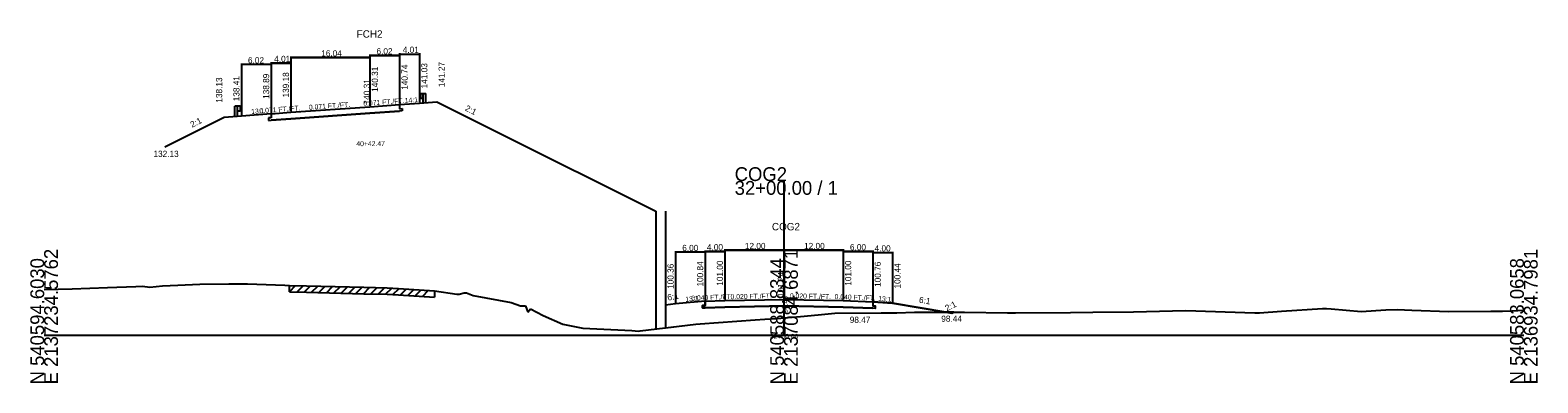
# Model space of a CAD drawing. Extents: x -13397 to 2303, y -10 to 39059.
# Drawn here: x 997.2 to 1302.8, y 3990.3 to 4061.8 of the extents above; entities that cross this region are included whole.
import ezdxf

# ---------------------------------------------------------------- set-up
doc = ezdxf.new("R2010")
doc.units = 0
for name, color, linetype in [('Level 20', 7, 'Continuous'), ('Level 5', 7, 'Continuous'), ('Level 53', 7, 'Continuous'), ('Level 54', 7, 'Continuous'), ('Level 55', 7, 'Continuous'), ('Level 7', 7, 'Continuous'), ('RD_GPK_XS_Cell', 7, 'Continuous'), ('RD_XS_EwShp', 7, 'Continuous'), ('RD_XS_ExGround', 7, 'Continuous'), ('RD_XS_ExPaveRet', 7, 'Continuous'), ('RD_XS_MedBWall', 7, 'Continuous'), ('RD_XS_Pave', 7, 'Continuous'), ('RD_XS_TX_Baseline', 7, 'Continuous'), ('RD_XS_TX_Elev_EX', 7, 'Continuous'), ('RD_XS_TX_Elev_PR', 7, 'Continuous'), ('RD_XS_TX_Station', 7, 'Continuous')]:
    doc.layers.add(name, color=color, linetype=linetype)

msp = doc.modelspace()

# ---------------------------------------------------------------- linework, layer by layer
at = {"layer": 'Level 20'}
for p, q in [((1050, 4056.46), (1050, 4045.38)), ((1050, 4056.46), (1050, 4045.38)), ((1050, 4056.46), (1050, 4045.38)), ((1050, 4056.46), (1050, 4045.38)), ((1066.04, 4056.89), (1066.04, 4046.51)), ((1066.04, 4056.89), (1066.04, 4046.51)), ((1066.04, 4056.89), (1066.04, 4046.51)), ((1066.04, 4056.69), (1072.06, 4056.69)), ((1072.06, 4056.69), (1066.04, 4056.69)), ((1072.06, 4056.69), (1066.04, 4056.69)), ((1066.04, 4056.46), (1066.04, 4046.51)), ((1066.04, 4056.46), (1066.04, 4046.51)), ((1066.04, 4056.46), (1066.04, 4046.51)), ((1066.04, 4056.46), (1066.04, 4046.51)), ((1072.06, 4057.18), (1072.06, 4046.94)), ((1072.06, 4056.98), (1076.07, 4056.98)), ((1072.06, 4056.89), (1072.06, 4046.94)), ((1072.06, 4056.89), (1072.06, 4046.94)), ((1072.06, 4056.89), (1072.06, 4046.94)), ((1076.07, 4057.18), (1076.07, 4047.23)), ((1039.98, 4055.04), (1039.98, 4044.61)), ((1045.99, 4054.84), (1039.98, 4054.84)), ((1045.99, 4055.33), (1045.99, 4045.09)), ((1045.99, 4055.33), (1045.99, 4045.09)), ((1045.99, 4055.33), (1045.99, 4045.09)), ((1045.99, 4055.13), (1050, 4055.13)), ((1045.99, 4055.13), (1050, 4055.13)), ((1050, 4055.13), (1045.99, 4055.13)), ((1045.99, 4055.04), (1045.99, 4045.09)), ((1050, 4056.26), (1066.04, 4056.26)), ((1050, 4056.26), (1066.04, 4056.26)), ((1066.04, 4056.26), (1050, 4056.26)), ((1066.04, 4056.26), (1050, 4056.26)), ((1050, 4055.33), (1050, 4045.38)), ((1050, 4055.33), (1050, 4045.38)), ((1050, 4055.33), (1050, 4045.38)), ((1076.07, 4047.03), (1079.58, 4047.27)), ((1076.09, 4048.84), (1076.21, 4048.93)), ((1076.09, 4048.74), (1076.21, 4048.65)), ((1076.09, 4048.31), (1076.21, 4048.4)), ((1076.09, 4048.21), (1076.21, 4048.12)), ((1076.22, 4048.94), (1076.3, 4048.95)), ((1076.22, 4048.11), (1076.3, 4048.1)), ((1076.23, 4048.6), (1076.23, 4048.45)), ((1076.3, 4049.01), (1076.3, 4048.04)), ((1076.3, 4049.01), (1076.85, 4049.01)), ((1076.3, 4048.04), (1076.85, 4048.04)), ((1076.85, 4047.03), (1076.85, 4049.01)), ((1076.85, 4049.01), (1077.41, 4049.01)), ((1077.41, 4047.03), (1077.41, 4049.01)), ((1079.58, 4047.27), (1091.61, 4041.27)), ((1039.98, 4044.41), (1036.47, 4044.13)), ((1038.64, 4044.41), (1038.64, 4046.4)), ((1039.2, 4046.4), (1038.64, 4046.4)), ((1039.2, 4044.41), (1039.2, 4046.4)), ((1039.75, 4046.4), (1039.2, 4046.4)), ((1039.75, 4045.43), (1039.2, 4045.43)), ((1039.75, 4046.4), (1039.75, 4045.43)), ((1039.82, 4046.32), (1039.75, 4046.34)), ((1039.82, 4045.5), (1039.75, 4045.49)), ((1039.82, 4045.99), (1039.82, 4045.83)), ((1039.95, 4046.23), (1039.84, 4046.32)), ((1039.95, 4046.13), (1039.84, 4046.03)), ((1039.95, 4045.7), (1039.84, 4045.79)), ((1039.95, 4045.6), (1039.84, 4045.5)), ((1045.99, 4044.89), (1039.98, 4044.41)), ((1045.99, 4044.89), (1050, 4045.18)), ((1045.99, 4044.89), (1045.99, 4044.06)), ((1050, 4045.18), (1066.04, 4046.31)), ((1066.04, 4044.98), (1050, 4043.84)), ((1066.04, 4044.98), (1050, 4043.84)), ((1050, 4043.84), (1066.04, 4044.98)), ((1050, 4043.84), (1066.04, 4044.98)), ((1066.04, 4046.31), (1072.06, 4046.74)), ((1072.06, 4045.41), (1066.04, 4044.98)), ((1066.04, 4044.98), (1072.06, 4045.41)), ((1066.04, 4044.98), (1072.06, 4045.41)), ((1072.06, 4046.74), (1076.07, 4047.03)), ((1072.06, 4046.74), (1072.06, 4045.91)), ((1072.06, 4045.91), (1072.56, 4045.94)), ((1072.56, 4045.44), (1072.06, 4045.41)), ((1072.56, 4045.94), (1072.56, 4045.44)), ((1036.47, 4044.13), (1024.44, 4038.13)), ((1045.99, 4044.06), (1045.49, 4044.02)), ((1045.49, 4044.02), (1045.49, 4043.52)), ((1045.49, 4043.52), (1045.99, 4043.56)), ((1050, 4043.84), (1045.99, 4043.56)), ((1050, 4043.84), (1045.99, 4043.56)), ((1045.99, 4043.56), (1050, 4043.84)), ((1091.61, 4041.27), (1124, 4025.12))]:
    msp.add_line(p, q, dxfattribs=at)
for centre, radius, start, end in [((1076.13, 4048.79), 0.0651, 129.0336, 230.9663), ((1076.13, 4048.26), 0.0651, 129.0336, 230.9663), ((1076.16, 4048.45), 0.0651, 302.9895, 0), ((1076.22, 4048.91), 0.026, 90, 129.0505), ((1076.16, 4048.6), 0.0651, 0, 45), ((1076.22, 4048.14), 0.026, 230.9496, 270), ((1039.82, 4046.3), 0.026, 50.9495, 90), ((1039.89, 4045.99), 0.0651, 135, 180), ((1039.89, 4045.83), 0.0651, 180, 237.0105), ((1039.82, 4045.53), 0.026, 270, 309.0504), ((1039.91, 4046.18), 0.0651, 309.0337, 50.9664), ((1039.91, 4045.65), 0.0651, 309.0337, 50.9664)]:
    msp.add_arc(centre, radius, start, end, dxfattribs=at)
at = {"layer": 'Level 5'}
for p, q in [((1134, 4006.01), (1133.5, 4005.99)), ((1133.5, 4005.99), (1133.5, 4005.49)), ((1133.5, 4005.49), (1134, 4005.51)), ((1134, 4006.84), (1134, 4006.01)), ((1138, 4005.67), (1134, 4005.51)), ((1138, 4005.67), (1134, 4005.51)), ((1138, 4005.67), (1134, 4005.51)), ((1134, 4005.51), (1138, 4005.67)), ((1150, 4005.91), (1138, 4005.67)), ((1150, 4005.91), (1138, 4005.67)), ((1150, 4005.91), (1138, 4005.67)), ((1138, 4005.67), (1150, 4005.91)), ((1138, 4005.67), (1150, 4005.91)), ((1162, 4005.67), (1150, 4005.91)), ((1162, 4005.67), (1150, 4005.91)), ((1150, 4005.91), (1162, 4005.67)), ((1150, 4005.91), (1162, 4005.67)), ((1150, 4005.91), (1162, 4005.67)), ((1168, 4005.43), (1162, 4005.67)), ((1162, 4005.67), (1168, 4005.43)), ((1162, 4005.67), (1168, 4005.43)), ((1162, 4005.67), (1168, 4005.43)), ((1168, 4006.76), (1168, 4005.93)), ((1168, 4005.93), (1168.5, 4005.91)), ((1168.5, 4005.41), (1168, 4005.43)), ((1168.5, 4005.91), (1168.5, 4005.41))]:
    msp.add_line(p, q, dxfattribs=at)
at = {"layer": 'Level 54'}
for p, q in [((1128, 4016.99), (1128, 4006.56)), ((1134, 4016.79), (1128, 4016.79)), ((1134, 4017.15), (1134, 4007.04)), ((1134, 4017.15), (1134, 4007.04)), ((1134, 4017.15), (1134, 4007.04)), ((1134, 4017.15), (1134, 4007.04)), ((1134, 4016.99), (1134, 4007.04)), ((1134, 4016.95), (1138, 4016.95)), ((1134, 4016.95), (1138, 4016.95)), ((1134, 4016.95), (1138, 4016.95)), ((1138, 4016.95), (1134, 4016.95)), ((1138, 4017.39), (1138, 4007.2)), ((1138, 4017.39), (1138, 4007.2)), ((1138, 4017.39), (1138, 4007.2)), ((1138, 4017.39), (1138, 4007.2)), ((1138, 4017.39), (1138, 4007.2)), ((1138, 4017.19), (1150, 4017.19)), ((1138, 4017.19), (1150, 4017.19)), ((1138, 4017.19), (1150, 4017.19)), ((1150, 4017.19), (1138, 4017.19)), ((1150, 4017.19), (1138, 4017.19)), ((1138, 4017.15), (1138, 4007.2)), ((1138, 4017.15), (1138, 4007.2)), ((1138, 4017.15), (1138, 4007.2)), ((1138, 4017.15), (1138, 4007.2)), ((1150, 4017.39), (1150, 4007.44)), ((1150, 4017.39), (1150, 4007.44)), ((1150, 4017.39), (1150, 4007.44)), ((1150, 4017.39), (1150, 4007.44)), ((1150, 4017.39), (1150, 4007.44)), ((1150, 4017.39), (1150, 4007.44)), ((1150, 4017.39), (1150, 4007.44)), ((1150, 4017.39), (1150, 4007.44)), ((1150, 4017.39), (1150, 4007.44)), ((1150, 4017.39), (1150, 4007.44)), ((1150, 4017.19), (1162, 4017.19)), ((1150, 4017.19), (1162, 4017.19)), ((1162, 4017.19), (1150, 4017.19)), ((1162, 4017.19), (1150, 4017.19)), ((1162, 4017.19), (1150, 4017.19)), ((1162, 4017.39), (1162, 4007.2)), ((1162, 4017.39), (1162, 4007.2)), ((1162, 4017.39), (1162, 4007.2)), ((1162, 4017.39), (1162, 4007.2)), ((1162, 4017.39), (1162, 4007.2)), ((1162, 4017.15), (1162, 4007.2)), ((1162, 4017.15), (1162, 4007.2)), ((1162, 4017.15), (1162, 4007.2)), ((1162, 4017.15), (1162, 4007.2)), ((1162, 4016.95), (1168, 4016.95)), ((1168, 4016.95), (1162, 4016.95)), ((1168, 4016.95), (1162, 4016.95)), ((1168, 4016.95), (1162, 4016.95)), ((1168, 4017.15), (1168, 4006.96)), ((1168, 4017.15), (1168, 4006.96)), ((1168, 4017.15), (1168, 4006.96)), ((1168, 4017.15), (1168, 4006.96)), ((1168, 4016.91), (1168, 4006.96)), ((1168, 4016.71), (1172, 4016.71)), ((1172, 4016.91), (1172, 4006.64))]:
    msp.add_line(p, q, dxfattribs=at)
at = {"layer": 'Level 7'}
for p, q in [((1128, 4006.36), (1126, 4006.03)), ((1126, 4006.03), (1126, 4001.45)), ((1134, 4006.84), (1128, 4006.36)), ((1168, 4006.76), (1172, 4006.44)), ((1172, 4006.44), (1184, 4004.44)), ((1184, 4004.44), (1184.41, 4004.64))]:
    msp.add_line(p, q, dxfattribs=at)
at = {"layer": 'RD_GPK_XS_Cell'}
for p, q in [((1150, 4000), (1150, 4031.24)), ((1000, 4000), (1150, 4000)), ((1150, 4000), (1300, 4000))]:
    msp.add_line(p, q, dxfattribs=at)
at = {"layer": 'RD_XS_EwShp'}
for points in [[(1128, 4006.36), (1126, 4006.03), (1126, 4001.45), (1132.12, 4002.18), (1132.97, 4002.28), (1144.16, 4003.11), (1146.1, 4003.21), (1148.69, 4003.38), (1150, 4003.49), (1153.34, 4003.76), (1156.94, 4004.12), (1160.29, 4004.44), (1169.73, 4004.49), (1172.85, 4004.51), (1176.43, 4004.61), (1182.82, 4004.64), (1172, 4006.44), (1168, 4006.76), (1168, 4005.93), (1168.5, 4005.91), (1168.5, 4005.41), (1168, 4005.43), (1162, 4005.67), (1150, 4005.91), (1138, 4005.67), (1134, 4005.51), (1133.5, 4005.49), (1133.5, 4005.99), (1134, 4006.01), (1134, 4006.84)], [(1182.82, 4004.64), (1184, 4004.44), (1184.41, 4004.64)]]:
    msp.add_lwpolyline(points, close=True, dxfattribs=at)
at = {"layer": 'RD_XS_ExGround'}
for p, q in [((1000, 4009.21), (1005.66, 4009.36)), ((1005.66, 4009.36), (1012.85, 4009.66)), ((1012.85, 4009.66), (1018.61, 4009.87)), ((1018.61, 4009.87), (1019.92, 4009.89)), ((1019.92, 4009.89), (1021.4, 4009.73)), ((1021.4, 4009.73), (1023.99, 4009.95)), ((1023.99, 4009.95), (1027.11, 4010.15)), ((1027.11, 4010.15), (1031.55, 4010.33)), ((1031.55, 4010.33), (1037.46, 4010.41)), ((1037.46, 4010.41), (1041.23, 4010.39)), ((1041.23, 4010.39), (1048.82, 4010.1)), ((1048.82, 4010.1), (1049.71, 4010.06)), ((1049.71, 4010.06), (1053.16, 4010)), ((1053.16, 4010), (1064.83, 4009.68)), ((1064.83, 4009.68), (1069.55, 4009.56)), ((1069.55, 4009.56), (1071.85, 4009.45)), ((1071.85, 4009.45), (1079.15, 4009)), ((1079.15, 4009), (1083.69, 4008.27)), ((1083.69, 4008.27), (1084.15, 4008.29)), ((1084.15, 4008.29), (1085.12, 4008.53)), ((1085.12, 4008.53), (1085.64, 4008.54)), ((1085.64, 4008.54), (1086.96, 4008.02)), ((1086.96, 4008.02), (1094.66, 4006.57)), ((1094.66, 4006.57), (1096.6, 4005.93)), ((1096.6, 4005.93), (1097.56, 4005.9)), ((1097.56, 4005.9), (1098.04, 4004.62)), ((1098.04, 4004.62), (1098.63, 4005.31)), ((1098.63, 4005.31), (1101.2, 4003.97)), ((1156.94, 4004.12), (1160.29, 4004.44)), ((1160.29, 4004.44), (1169.73, 4004.49)), ((1169.73, 4004.49), (1172.85, 4004.51)), ((1172.85, 4004.51), (1176.43, 4004.61)), ((1176.43, 4004.61), (1186.58, 4004.65)), ((1186.58, 4004.65), (1195.29, 4004.53)), ((1195.29, 4004.53), (1196.03, 4004.51)), ((1196.03, 4004.51), (1196.92, 4004.53)), ((1196.92, 4004.53), (1208.08, 4004.59)), ((1208.08, 4004.59), (1212.63, 4004.62)), ((1212.63, 4004.62), (1220.86, 4004.69)), ((1220.86, 4004.69), (1228.75, 4004.88)), ((1228.75, 4004.88), (1231.47, 4005)), ((1231.47, 4005), (1245.45, 4004.53)), ((1245.45, 4004.53), (1246.01, 4004.53)), ((1246.01, 4004.53), (1246.43, 4004.51)), ((1246.43, 4004.51), (1250.87, 4004.83)), ((1250.87, 4004.83), (1259.21, 4005.36)), ((1259.21, 4005.36), (1259.99, 4005.41)), ((1259.99, 4005.41), (1260.96, 4005.29)), ((1260.96, 4005.29), (1267.05, 4004.78)), ((1267.05, 4004.78), (1271.99, 4005.09)), ((1271.99, 4005.09), (1274.29, 4005.2)), ((1274.29, 4005.2), (1277.27, 4005.07)), ((1277.27, 4005.07), (1284.78, 4004.79)), ((1284.78, 4004.79), (1293.34, 4004.86)), ((1293.34, 4004.86), (1295.65, 4004.86)), ((1295.65, 4004.86), (1297.56, 4004.94)), ((1297.56, 4004.94), (1300, 4005.03)), ((1101.2, 4003.97), (1105.17, 4002.24)), ((1105.17, 4002.24), (1109.21, 4001.39)), ((1109.21, 4001.39), (1119.14, 4000.91)), ((1120.87, 4000.84), (1132.12, 4002.18)), ((1132.12, 4002.18), (1132.97, 4002.28)), ((1132.97, 4002.28), (1144.16, 4003.11)), ((1144.16, 4003.11), (1146.1, 4003.21)), ((1146.1, 4003.21), (1148.69, 4003.38)), ((1148.69, 4003.38), (1150, 4003.49)), ((1150, 4003.49), (1153.34, 4003.76)), ((1153.34, 4003.76), (1156.94, 4004.12)), ((1119.14, 4000.91), (1120.47, 4000.8)), ((1120.47, 4000.8), (1120.87, 4000.84))]:
    msp.add_line(p, q, dxfattribs=at)
at = {"layer": 'RD_XS_ExPaveRet'}
for p, q in [((1049.71, 4008.76), (1049.71, 4010.06)), ((1049.71, 4008.76), (1050.99, 4010.04)), ((1049.71, 4008.76), (1053.16, 4008.7)), ((1051.21, 4008.73), (1052.49, 4010.01)), ((1052.72, 4008.71), (1053.98, 4009.98)), ((1053.16, 4008.7), (1064.83, 4008.38)), ((1054.22, 4008.67), (1055.48, 4009.93)), ((1055.72, 4008.63), (1056.98, 4009.89)), ((1057.22, 4008.59), (1058.48, 4009.85)), ((1058.72, 4008.55), (1059.98, 4009.81)), ((1060.22, 4008.5), (1061.48, 4009.77)), ((1061.72, 4008.46), (1062.98, 4009.73)), ((1063.22, 4008.42), (1064.48, 4009.69)), ((1064.72, 4008.38), (1065.98, 4009.65)), ((1064.83, 4008.38), (1069.55, 4008.26)), ((1066.22, 4008.34), (1067.48, 4009.61)), ((1067.72, 4008.3), (1068.98, 4009.57)), ((1069.22, 4008.27), (1070.46, 4009.51)), ((1069.55, 4008.26), (1071.85, 4008.15)), ((1070.72, 4008.2), (1071.96, 4009.44)), ((1071.85, 4008.15), (1079.15, 4007.7)), ((1072.22, 4008.13), (1073.44, 4009.35)), ((1073.72, 4008.03), (1074.94, 4009.26)), ((1075.22, 4007.94), (1076.44, 4009.17)), ((1076.72, 4007.85), (1077.94, 4009.08)), ((1079.15, 4009), (1079.15, 4007.7))]:
    msp.add_line(p, q, dxfattribs=at)
at = {"layer": 'RD_XS_MedBWall'}
for p, q in [((1124, 4025.12), (1124, 4001.21)), ((1126, 4025.12), (1126, 4006.03))]:
    msp.add_line(p, q, dxfattribs=at)
at = {"layer": 'RD_XS_Pave'}
for p, q in [((1134, 4006.84), (1138, 4007)), ((1138, 4007), (1150, 4007.24)), ((1150, 4007.24), (1162, 4007)), ((1162, 4007), (1168, 4006.76))]:
    msp.add_line(p, q, dxfattribs=at)

# ---------------------------------------------------------------- texts
at = {"layer": 'Level 20'}
for s, height, p in [('FCH2', 1.5, (1063.36, 4060.31)), ('4.01', 1.25, (1046.64, 4055.38)), ('4.01', 1.25, (1046.64, 4055.38)), ('4.01', 1.25, (1046.64, 4055.38)), ('16.04', 1.25, (1056.17, 4056.51)), ('16.04', 1.25, (1056.17, 4056.51)), ('16.04', 1.25, (1056.17, 4056.51)), ('16.04', 1.25, (1056.17, 4056.51)), ('6.02', 1.25, (1067.38, 4056.94)), ('6.02', 1.25, (1067.38, 4056.94)), ('6.02', 1.25, (1067.38, 4056.94)), ('4.01', 1.25, (1072.71, 4057.23)), ('6.02', 1.25, (1041.32, 4055.09)), ('40+42.47', 1, (1063.29, 4038.31)), ('132.13', 1.25, (1022.16, 4036.13))]:
    msp.add_text(s, height=height, dxfattribs=at).set_placement(p)
for s, height, rotation, p in [('140.31', 1.25, 90, (1067.67, 4049.31)), ('140.31', 1.25, 90, (1067.67, 4049.31)), ('140.74', 1.25, 90, (1073.69, 4049.74)), ('141.03', 1.25, 90, (1077.7, 4050.03)), ('141.27', 1.25, 90, (1081.21, 4050.27)), ('138.13', 1.25, 90, (1036.09, 4047.13)), ('138.41', 1.25, 90, (1039.6, 4047.41)), ('138.89', 1.25, 90, (1045.62, 4047.89)), ('139.18', 1.25, 90, (1049.63, 4048.18)), ('139.18', 1.25, 90, (1049.63, 4048.18)), (' 140.31', 1.25, 90, (1066.04, 4046.31)), ('0.071 FT./FT.', 1, 4.0605, (1053.71, 4045.69)), ('0.071 FT./FT.', 1, 4.0605, (1053.71, 4045.69)), ('0.071 FT./FT.', 1, 4.0605, (1053.71, 4045.69)), ('0.071 FT./FT.', 1, 4.0605, (1053.71, 4045.69)), ('0.071 FT./FT.', 1, 4.0616, (1064.73, 4046.47)), ('0.071 FT./FT.', 1, 4.0616, (1064.73, 4046.47)), ('0.071 FT./FT.', 1, 4.0616, (1064.73, 4046.47)), ('14:1', 1, 4.0515, (1073.15, 4047.07)), ('13:1', 1, 4.562, (1042.01, 4044.82)), ('0.071 FT./FT.', 1, 4.0595, (1043.68, 4044.98)), ('0.071 FT./FT.', 1, 4.0595, (1043.68, 4044.98)), ('0.071 FT./FT.', 1, 4.0595, (1043.68, 4044.98)), ('2:1', 1.25, 333.4922, (1085.2, 4045.59)), ('2:1', 1.25, 26.5051, (1030.01, 4042.03))]:
    msp.add_text(s, height=height, rotation=rotation, dxfattribs=at).set_placement(p)
at = {"layer": 'Level 53'}
for s, rotation, p in [('100.36', 90, (1127.62, 4009.36)), ('100.84', 90, (1133.62, 4009.84)), ('101.00', 90, (1137.63, 4010)), ('101.00', 90, (1137.63, 4010)), ('101.00', 90, (1137.63, 4010)), ('101.00', 90, (1163.62, 4010)), ('101.00', 90, (1163.62, 4010)), ('101.00', 90, (1163.62, 4010)), ('100.76', 90, (1169.62, 4009.76)), ('100.44', 90, (1173.62, 4009.44)), ('6:1', 9.4623, (1126.46, 4006.99)), ('6:1', 350.5377, (1177.3, 4006.57))]:
    msp.add_text(s, height=1.25, rotation=rotation, dxfattribs=at).set_placement(p)
for s, p in [('98.47', (1163.33, 4002.47)), ('98.44', (1181.89, 4002.69))]:
    msp.add_text(s, height=1.25, dxfattribs=at).set_placement(p)
at = {"layer": 'Level 54'}
for s, p in [('6.00', (1129.37, 4017.04)), ('4.00', (1134.37, 4017.2)), ('4.00', (1134.37, 4017.2)), ('4.00', (1134.37, 4017.2)), ('4.00', (1134.37, 4017.2)), ('12.00', (1142.07, 4017.44)), ('12.00', (1142.07, 4017.44)), ('12.00', (1142.07, 4017.44)), ('12.00', (1142.07, 4017.44)), ('12.00', (1142.07, 4017.44)), ('12.00', (1154.07, 4017.44)), ('12.00', (1154.07, 4017.44)), ('12.00', (1154.07, 4017.44)), ('12.00', (1154.07, 4017.44)), ('12.00', (1154.07, 4017.44)), ('6.00', (1163.37, 4017.2)), ('6.00', (1163.37, 4017.2)), ('6.00', (1163.37, 4017.2)), ('6.00', (1163.37, 4017.2)), ('4.00', (1168.37, 4016.96))]:
    msp.add_text(s, height=1.25, dxfattribs=at).set_placement(p)
at = {"layer": 'Level 55'}
for s, height, rotation, p in [('13:1', 1, 4.5739, (1130.03, 4006.77)), ('0.040 FT./FT.', 1, 2.2906, (1131.22, 4006.98)), ('0.040 FT./FT.', 1, 2.2906, (1131.22, 4006.98)), ('0.040 FT./FT.', 1, 2.2906, (1131.22, 4006.98)), ('0.040 FT./FT.', 1, 2.2906, (1131.22, 4006.98)), ('0.020 FT./FT.', 1, 1.1458, (1139.17, 4007.27)), ('0.020 FT./FT.', 1, 1.1458, (1139.17, 4007.27)), ('0.020 FT./FT.', 1, 1.1458, (1139.17, 4007.27)), ('0.020 FT./FT.', 1, 1.1458, (1139.17, 4007.27)), ('0.020 FT./FT.', 1, 1.1458, (1139.17, 4007.27)), ('0.020 FT./FT.', 1, 358.8542, (1151.18, 4007.47)), ('0.020 FT./FT.', 1, 358.8542, (1151.18, 4007.47)), ('0.020 FT./FT.', 1, 358.8542, (1151.18, 4007.47)), ('0.020 FT./FT.', 1, 358.8542, (1151.18, 4007.47)), ('0.020 FT./FT.', 1, 358.8542, (1151.18, 4007.47)), ('0.040 FT./FT.', 1, 357.7094, (1160.24, 4007.32)), ('0.040 FT./FT.', 1, 357.7094, (1160.24, 4007.32)), ('0.040 FT./FT.', 1, 357.7094, (1160.24, 4007.32)), ('0.040 FT./FT.', 1, 357.7094, (1160.24, 4007.32)), ('13:1', 1, 355.4261, (1169.07, 4006.93)), ('2:1', 1.25, 26.5651, (1183.03, 4004.79))]:
    msp.add_text(s, height=height, rotation=rotation, dxfattribs=at).set_placement(p)
at = {"layer": 'RD_GPK_XS_Cell'}
for s, p in [('COG2', (1140, 4031.24)), ('32+00.00 / 1', (1140, 4028.44))]:
    msp.add_text(s, height=2.8, dxfattribs=at).set_placement(p)
for s, p in [('E 2137234.5762', (1002.8, 3990)), ('E 2137084.6871', (1152.8, 3990)), ('E 2136934.7981', (1302.8, 3990)), ('N 540594.6030', (1000, 3990)), ('N 540588.8344', (1150, 3990)), ('N 540583.0658', (1300, 3990))]:
    msp.add_text(s, height=2.8, rotation=90, dxfattribs=at).set_placement(p)
at = {"layer": 'RD_XS_TX_Baseline'}
msp.add_text('COG2', height=1.5, dxfattribs=at).set_placement((1147.55, 4021.24))
at = {"layer": 'RD_XS_TX_Elev_EX'}
msp.add_text('97.49', height=1, rotation=90, dxfattribs=at).set_placement((1150.75, 4004.49))
at = {"layer": 'RD_XS_TX_Elev_PR'}
msp.add_text(' 101.24', height=1.25, rotation=90, dxfattribs=at).set_placement((1150, 4007.24))
at = {"layer": 'RD_XS_TX_Station'}
msp.add_text('32+00.00', height=1, dxfattribs=at).set_placement((1147.12, 3999.24))

doc.saveas('drawing.dxf')
